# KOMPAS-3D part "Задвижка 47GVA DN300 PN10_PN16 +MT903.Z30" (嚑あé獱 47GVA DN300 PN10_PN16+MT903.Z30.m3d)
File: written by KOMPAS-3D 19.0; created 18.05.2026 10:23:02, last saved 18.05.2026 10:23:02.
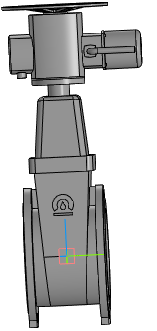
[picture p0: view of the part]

Document properties: Автор: Энергия; Полное имя файла: ..\Задвижка 47GVA DN50_DN1000+MT903.Z\Задвижка 47GVA DN300 PN10_PN16+MT903.Z30.a3d

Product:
- Part/product: Задвижка 47GVA DN300 PN10_PN16 +MT903.Z30
    Масса: 321.956
  - Body: Электропривод MT903.Z20-30
      Масса: 83.2154
  - Body: Задвижка 47GVA DN300 PN10_PN16 без исполнит. мех.
      Масса: 238.74

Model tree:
1. Операция без истории:1
2. Операция без истории:2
